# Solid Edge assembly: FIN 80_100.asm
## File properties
Title: Zylinder
Author: bmolnar
Template: iso assembly.asm
Last saved by: bmolnar
Revision: 17
Application: Solid Edge
Username: bmolnar
Dokumentum tartalom típus: 1
Document Number: FIN 80/100
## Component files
Kolbenstange.par
Profilrohr.par
Kit_1.par
Kit_2.par
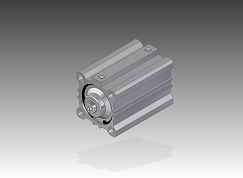
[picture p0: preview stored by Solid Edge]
